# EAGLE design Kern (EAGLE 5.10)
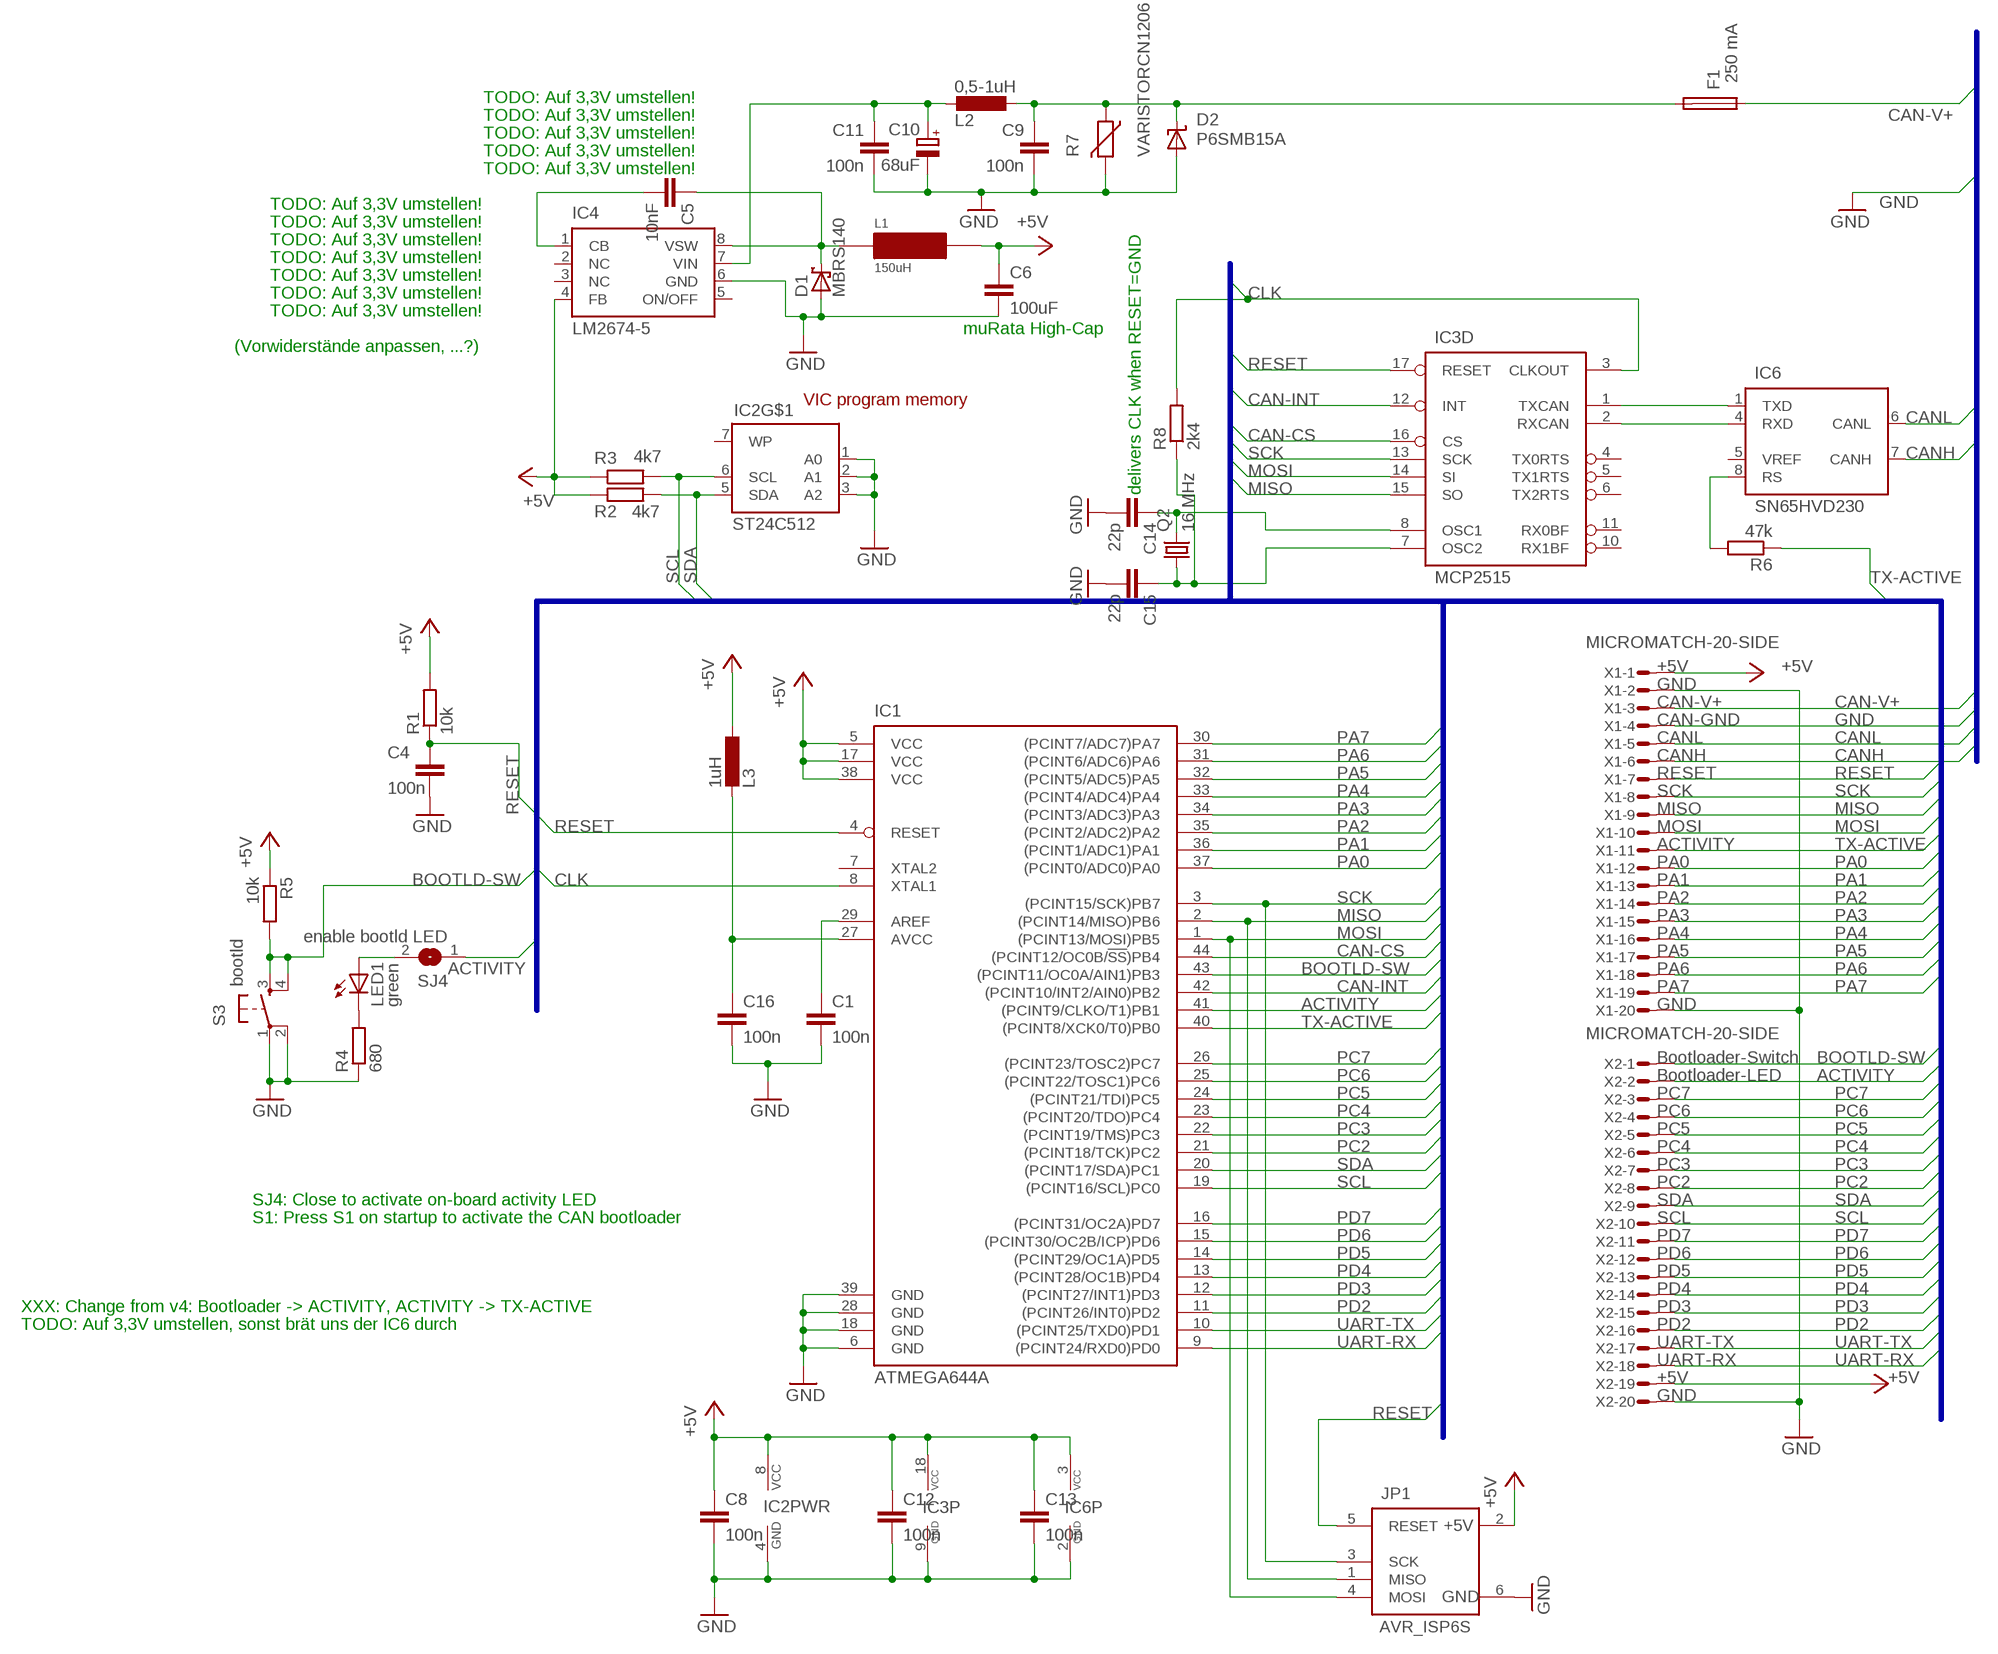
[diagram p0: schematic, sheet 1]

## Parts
C1  100n  C-EUC0805  [C0805]
C4  100n  C-EUC0805  [C0805]
C5  10nF  C-EUC0805  [C0805]
C6  100uF  C-EUC1206  [C1206]
C8  100n  C-EUC0805  [C0805]
C9  100n  C-EUC0805  [C0805]
C10  68uF  CPOL-EUD  [PANASONIC_D]
C11  100n  C-EUC0805  [C0805]
C12  100n  C-EUC0805  [C0805]
C13  100n  C-EUC0805  [C0805]
C14  22p  C-EUC0805  [C0805]
C15  22p  C-EUC0805  [C0805]
C16  100n  C-EUC0805  [C0805]
D1  MBRS140  MBRS130LT3  [SMB]
D2  P6SMB15A  P6SMBXXA  [SMB]
F1  250 mA  SICHERUNG-SMD  [SMD-HASF]
IC1  ATMEGA644A  [TQFP44]
IC2  ST24C512  ST24CXX_DIP  [DIL08]
IC3  MCP2515  MCP2515SO  [SO-18W]
IC4  LM2674-5  LM2674  [SO8]
IC6  SN65HVD230  PCA82C250  [DIL08]
JP1  AVR_ISP6S  [LEISTE_2X03]
L1  150uH  SPULEN-PIS28XX  [L-PIS28XX]
L2  0,5-1uH  L-EUL3216C  [L3216C]
L3  1uH  L-EUL3216C  [L3216C]
LED1  green  LEDCHIP-LED0805  [CHIP-LED0805]
Q2  16 MHz  CRYSTALHC49UP  [HC49UP]
R1  10k  R-EU_R0805  [R0805]
R2  4k7  R-EU_R0805  [R0805]
R3  4k7  R-EU_R0805  [R0805]
R4  680  R-EU_R0805  [R0805]
R5  10k  R-EU_R0805  [R0805]
R6  47k  R-EU_R0805  [R0805]
R7  VARISTORCN1206  [CT/CN1206]
R8  2k4  R-EU_R0805  [R0805]
S3  bootld  LSG  [SCHURTER_LSG]
SJ4  enable bootld LED  SJ  [SJ]
X1  MICROMATCH-20-SIDE  [MICROMATCH-20-SIDE]
X2  MICROMATCH-20-SIDE  [MICROMATCH-20-SIDE]

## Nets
+5V: C6.1 C8.1 C12.1 C13.1 IC1.5(VCC) IC1.17(VCC) IC1.38(VCC) IC2.8(PWR:VCC) IC3.18(P:VCC) IC4.4(FB) IC6.3(VCC) JP1.2(+5V) L1.2 L3.1 R1.2 R2.1 R3.1 R5.1 X1.1 X2.19
ACTIVITY: IC1.41((PCINT9/CLKO/T1)PB1) SJ4.1 X2.2
BOOTLD-SW: IC1.43((PCINT11/OC0A/AIN1)PB3) R5.2 S3.3(S) S3.4(S1) X2.1
CAN-CS: IC1.44((PCINT12/OC0B/!SS!)PB4) IC3.16(D:CS)
CAN-INT: IC1.42((PCINT10/INT2/AIN0)PB2) IC3.12(D:INT)
CAN-V+ [Power]: F1.1 X1.3
CANH: IC6.7(CANH) X1.6
CANL: IC6.6(CANL) X1.5
CLK: IC1.8(XTAL1) IC3.3(D:CLKOUT) R8.2
GND: C1.2 C4.2 C6.2 C8.2 C9.2 C10.- C11.2 C12.2 C13.2 C14.2 C15.2 C16.2 D1.A D2.A IC1.6(GND) IC1.18(GND) IC1.28(GND) IC1.39(GND) IC2.1(A0) IC2.2(A1) IC2.3(A2) IC2.4(PWR:GND) IC3.9(P:GND) IC4.6(GND) IC6.2(GND) JP1.6(GND) R4.1 R7.2 S3.1(P) S3.2(P1) X1.2 X1.4 X1.20 X2.20
MISO: IC1.2((PCINT14/MISO)PB6) IC3.15(D:SO) JP1.1(MISO) X1.9
MOSI: IC1.1((PCINT13/MOSI)PB5) IC3.14(D:SI) JP1.4(MOSI) X1.10
N$2: C5.1 D1.C IC4.8(VSW) L1.1
N$3: C1.1 IC1.29(AREF)
N$5 [Power]: C9.1 D2.C F1.2 L2.1 R7.1
N$6: LED1.C R4.2
N$7: C5.2 IC4.1(CB)
N$8 [Power]: C10.+ C11.1 IC4.7(VIN) L2.2
N$9: LED1.A SJ4.2
N$11: IC6.8(RS) R6.2
N$12: C14.1 IC3.8(D:OSC1) Q2.2
N$13: IC3.1(D:TXCAN) IC6.1(TXD)
N$14: IC3.2(D:RXCAN) IC6.4(RXD)
N$15: C16.1 IC1.27(AVCC) L3.2
N$16: C15.1 IC3.7(D:OSC2) Q2.1 R8.1
PA0: IC1.37((PCINT0/ADC0)PA0) X1.12
PA1: IC1.36((PCINT1/ADC1)PA1) X1.13
PA2: IC1.35((PCINT2/ADC2)PA2) X1.14
PA3: IC1.34((PCINT3/ADC3)PA3) X1.15
PA4: IC1.33((PCINT4/ADC4)PA4) X1.16
PA5: IC1.32((PCINT5/ADC5)PA5) X1.17
PA6: IC1.31((PCINT6/ADC6)PA6) X1.18
PA7: IC1.30((PCINT7/ADC7)PA7) X1.19
PC2: IC1.21((PCINT18/TCK)PC2) X2.8
PC3: IC1.22((PCINT19/TMS)PC3) X2.7
PC4: IC1.23((PCINT20/TDO)PC4) X2.6
PC5: IC1.24((PCINT21/TDI)PC5) X2.5
PC6: IC1.25((PCINT22/TOSC1)PC6) X2.4
PC7: IC1.26((PCINT23/TOSC2)PC7) X2.3
PD2: IC1.11((PCINT26/INT0)PD2) X2.16
PD3: IC1.12((PCINT27/INT1)PD3) X2.15
PD4: IC1.13((PCINT28/OC1B)PD4) X2.14
PD5: IC1.14((PCINT29/OC1A)PD5) X2.13
PD6: IC1.15((PCINT30/OC2B/ICP)PD6) X2.12
PD7: IC1.16((PCINT31/OC2A)PD7) X2.11
RESET: C4.1 IC1.4(RESET) IC3.17(D:RESET) JP1.5(RESET) R1.1 X1.7
SCK: IC1.3((PCINT15/SCK)PB7) IC3.13(D:SCK) JP1.3(SCK) X1.8
SCL: IC1.19((PCINT16/SCL)PC0) IC2.6(SCL) R3.2 X2.10
SDA: IC1.20((PCINT17/SDA)PC1) IC2.5(SDA) R2.2 X2.9
TX-ACTIVE: IC1.40((PCINT8/XCK0/T0)PB0) R6.1 X1.11
UART-RX: IC1.9((PCINT24/RXD0)PD0) X2.18
UART-TX: IC1.10((PCINT25/TXD0)PD1) X2.17
Unconnected: IC1.7(XTAL2) IC2.7(WP) IC3.4(D:TX0RTS) IC3.5(D:TX1RTS) IC3.6(D:TX2RTS) IC3.10(D:RX1BF) IC3.11(D:RX0BF) IC4.2(NC) IC4.3(NC) IC4.5(ON/OFF) IC6.5(VREF)

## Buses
PA[0..7],PC[2..7],PD[2..7],SCK,MISO,MOSI,CAN-CS,BOOTLD-SW,CAN-INT,TX-ACTIVE,ACTIVITY,SDA,SCL,UART-RX,UART-TX,CLK,RESET
CANL,CANH,CAN-V+,CAN-GND,GND

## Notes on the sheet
- TODO: Auf 3,3V umstellen!
- TODO: Auf 3,3V umstellen!
- TODO: Auf 3,3V umstellen!
- TODO: Auf 3,3V umstellen!
- TODO: Auf 3,3V umstellen!
- TODO: Auf 3,3V umstellen!
- TODO: Auf 3,3V umstellen!
- TODO: Auf 3,3V umstellen!
- TODO: Auf 3,3V umstellen!
- TODO: Auf 3,3V umstellen!
- TODO: Auf 3,3V umstellen!
- TODO: Auf 3,3V umstellen!
- muRata High-Cap
- (Vorwiderstände anpassen, ...?)
- VIC program memory
- delivers CLK when RESET=GND
- +5V
- GND
- CAN-V+
- CAN-GND
- CANL
- CANH
- RESET
- SCK
- MISO
- MOSI
- ACTIVITY
- PA0
- PA1
- PA2
- PA3
- PA4
- PA5
- PA6
- PA7
- GND
- Bootloader-Switch
- Bootloader-LED
- PC7
- PC6
- PC5
- PC4
- PC3
- PC2
- SJ4: Close to activate on-board activity LED | SDA
- S1: Press S1 on startup to activate the CAN bootloader | SCL
- PD7
- PD6
- PD5
- PD4
- XXX: Change from v4: Bootloader -> ACTIVITY, ACTIVITY -> TX-ACTIVE | PD3
- TODO: Auf 3,3V umstellen, sonst brät uns der IC6 durch | PD2
- UART-TX
- UART-RX
- +5V
- GND

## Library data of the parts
C1 C4-C6 C8 C9 C11-C16 = rcl:C-EU: CAPACITOR, European symbol
C10 = rcl:CPOL-EU: POLARIZED CAPACITOR, European symbol
D1 = diode:MBRS130LT3: Schottky Power Rectifier
D2 = 11my-ICs:P6SMBXXA: Suppressor diode
F1 = 11my-RCA:SICHERUNG: Fuse
IC1 = atmel:ATMEGA644: 8-bit Microcontroller with 64K Bytes In-System Programmable Flash Source: http://www.atmel.com/dyn/resources/prod_documents/doc2593.pdf
IC2 = 11my-ICs:ST24CXX: I²C EEPROM Bei den Atmeltypen ist der A2-Pin nicht angeschlossen! Bisher überprfte Größen: ST24C32 (4 kByte) ST24C64 (8 kByte) ST24C128 (16 kByte) ST24C256 (32 kByte)
IC3 = 11my-CAN:MCP2515: MC2515 Stand-Alone CAN Controller With SPI Interface
IC4 = lm2674-auml.se:LM2674
IC6 = 11my-CAN:PCA82C250: PCA82C250 CAN Bustreiber
JP1 = 11my-AVR:AVR_ISP6: ISP (In System Programming) Stecker fr AVRs ber diesen Anschlu kann ein AVR mit einem Standard ISP-Kabel direkt an einen Parallelport des PCs angeschlossen und programmiert werden.
L1 = 11my-RCA:SPULEN: SMD-Power-Induktivitten
L2 L3 = rcl:L-EU: INDUCTOR, European symbol
LED1 = led:LED: LED
Q2 = crystal:CRYSTAL: CRYSTAL
R1-R6 R8 = rcl:R-EU_: RESISTOR, European symbol
R7 = varistor:VARISTOR: VARISTOR
S3 = 11my-mechanics:LSG: Schurter LSG SMD-Taster
SJ4 = jumper:SJ: SMD solder JUMPER
X1 X2 = apbteam_con-amp-micromatch:MICROMATCH-20: Micro-MaTch 20 Straight connector: Suited for both, female and male.

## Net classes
0 default: width 0.15 mm
1 Power: width 0.5 mm

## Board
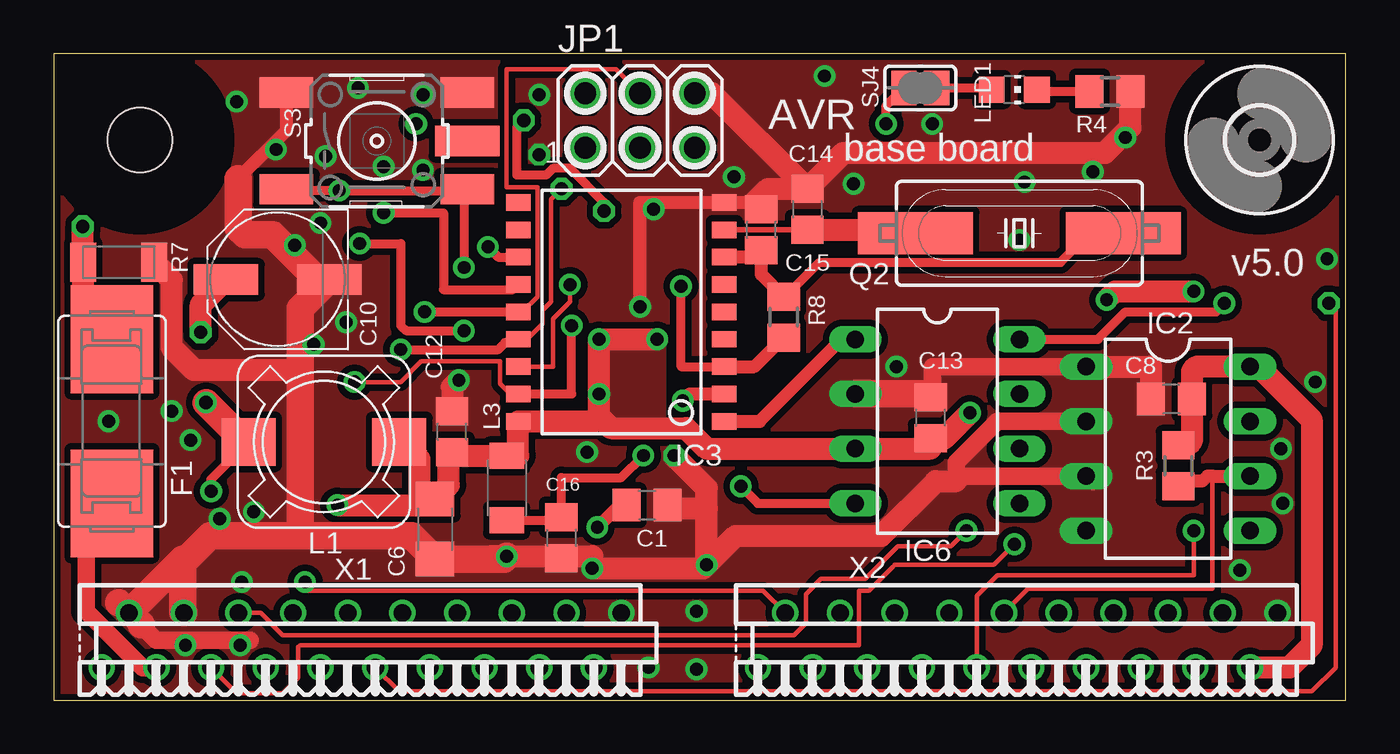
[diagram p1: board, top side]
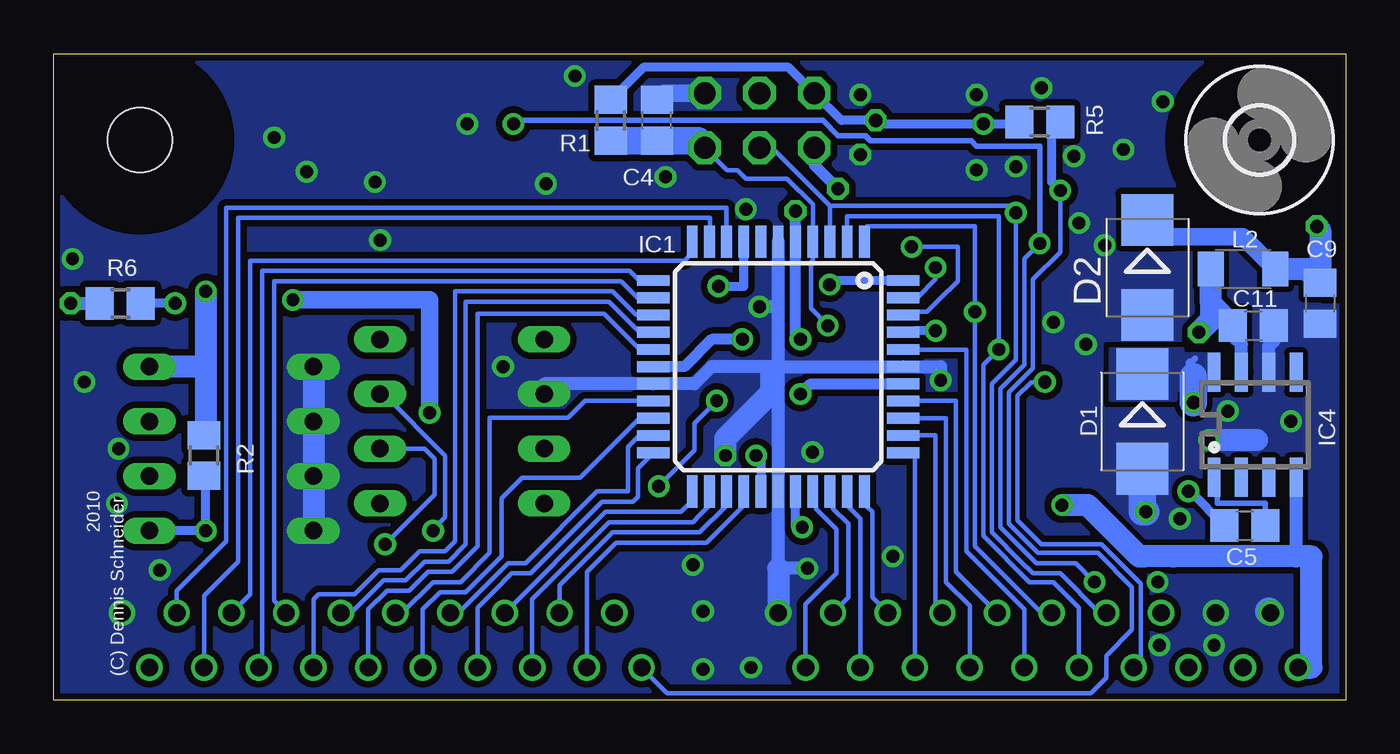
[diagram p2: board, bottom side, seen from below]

Size 60 x 30 mm. Coordinates in mm from the lower left corner, seen from the top.
Outline: 0,0 60,0 60,30 0,30 0,0
Copper layers (1+2*15+16): Top 0.035mm / dielectric 0.36mm / Route2 0.018mm / dielectric 0.71mm / Route15 0.018mm / dielectric 0.36mm / Bottom 0.035mm
Design rules "q-print.info *": minimum track width 6mil, minimum drill 0.3mm, track to track 6mil, track to pad 6mil, pad to pad 6mil, via to via 6mil, smd to smd 6mil, copper to edge 8mil, drill to drill 10mil, minimum pad ring 8mil, minimum via ring 8mil, stop-mask expansion 4mil, vias tented up to drill 16mil, thermal gap 10mil

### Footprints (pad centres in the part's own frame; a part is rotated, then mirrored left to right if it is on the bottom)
C0805 = smd 1.3 x 1.5: 1 -0.95,0; 2 0.95,0
C1206 = smd 1.6 x 1.8: 1 -1.4,0; 2 1.4,0
PANASONIC_D = smd 3 x 1.4: + 2.4,0; - -2.4,0
SMB = smd 2.4 x 2.4: A 2.2,0; C -2.2,0
SMD-HASF = smd 5 x 3.81: 1 -3.81,0; 2 3.81,0
TQFP44 = smd 1.5 x 0.5: 1 -5.8,4; 2 -5.8,3.2; 3 -5.8,2.4; 4 -5.8,1.6; 5 -5.8,0.8; 6 -5.8,0; 7 -5.8,-0.8; 8 -5.8,-1.6; 9 -5.8,-2.4; 10 -5.8,-3.2; 11 -5.8,-4; 23 5.8,-4; 24 5.8,-3.2; 25 5.8,-2.4; 26 5.8,-1.6; 27 5.8,-0.8; 28 5.8,0; 29 5.8,0.8; 30 5.8,1.6; 31 5.8,2.4; 32 5.8,3.2; 33 5.8,4 | smd 0.5 x 1.5: 12 -4,-5.8; 13 -3.2,-5.8; 14 -2.4,-5.8; 15 -1.6,-5.8; 16 -0.8,-5.8; 17 0,-5.8; 18 0.8,-5.8; 19 1.6,-5.8; 20 2.4,-5.8; 21 3.2,-5.8; 22 4,-5.8; 34 4,5.8; 35 3.2,5.8; 36 2.4,5.8; 37 1.6,5.8; 38 0.8,5.8; 39 0,5.8; 40 -0.8,5.8; 41 -1.6,5.8; 42 -2.4,5.8; 43 -3.2,5.8; 44 -4,5.8
DIL08 = drill 0.813 long: 1 -3.81,-3.81; 2 -1.27,-3.81; 3 1.27,-3.81; 4 3.81,-3.81; 5 3.81,3.81; 6 1.27,3.81; 7 -1.27,3.81; 8 -3.81,3.81
SO-18W = smd 0.762 x 1.143: 1 -5.08,-4.788; 2 -3.81,-4.788; 3 -2.54,-4.788; 4 -1.27,-4.788; 5 0,-4.788; 6 1.27,-4.788; 7 2.54,-4.788; 8 3.81,-4.788; 9 5.08,-4.788; 10 5.08,4.788; 11 3.81,4.788; 12 2.54,4.788; 13 1.27,4.788; 14 0,4.788; 15 -1.27,4.788; 16 -2.54,4.788; 17 -3.81,4.788; 18 -5.08,4.788
SO8 = smd 0.6 x 1.8: 1 -1.905,-2.44; 2 -0.635,-2.44; 3 0.635,-2.44; 4 1.905,-2.44; 5 1.905,2.44; 6 0.635,2.44; 7 -0.635,2.44; 8 -1.905,2.44
LEISTE_2X03 = drill 1.016 octagon: 1 -2.54,-1.27; 2 -2.54,1.27; 3 0,-1.27; 4 0,1.27; 5 2.54,-1.27; 6 2.54,1.27
L-PIS28XX = smd 2.2 x 2.5: 1 0,3.5; 2 0,-3.5
L3216C = smd 1.2 x 1.6: 1 -1.5,0; 2 1.5,0
CHIP-LED0805 = smd 1.2 x 1.2: A 0,-1.05; C 0,1.05
HC49UP = smd 5.334 x 1.93: 1 -4.826,0; 2 4.826,0
R0805 = smd 1.3 x 1.5: 1 -0.95,0; 2 0.95,0
CT/CN1206 = smd 1.2 x 1.8: 1 -1.65,0; 2 1.65,0
SCHURTER_LSG = smd 2.5 x 1.4: 1 -4.2,2.25; 2 4.2,2.25; 3 -4.2,-2.25; 4 4.2,-2.25 | smd 3 x 1.4: 5 4.2,0
SJ = smd 1.168 x 1.6: 1 -0.762,0; 2 0.762,0
3,0 = hole 3: 0,0
MICROMATCH-20-SIDE = drill 0.813 round: 1 12.065,1.27; 2 10.795,-1.27; 3 9.525,1.27; 4 8.255,-1.27; 5 6.985,1.27; 6 5.715,-1.27; 7 4.445,1.27; 8 3.175,-1.27; 9 1.905,1.27; 10 0.635,-1.27; 11 -0.635,1.27; 12 -1.905,-1.27; 13 -3.175,1.27; 14 -4.445,-1.27; 15 -5.715,1.27; 16 -6.985,-1.27; 17 -8.255,1.27; 18 -9.525,-1.27; 19 -10.795,1.27; 20 -12.065,-1.27

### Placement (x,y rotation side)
C1  27.54,9.05 0 top
C4  31.99,26.91 90 bottom
C5  4.68,8.1 0 bottom
C6  17.7,7.94 270 top
C8  51.91,13.97 180 top
C9  1.19,18.42 270 bottom
C10  10.4,19.53 180 top
C11  4.29,17.38 0 bottom
C12  18.49,12.46 90 top
C13  40.72,13.1 90 top
C14  35,22.78 90 top
C15  32.86,21.83 90 top
C16  23.57,7.54 270 top
D1  9.45,12.94 270 bottom
D2  9.21,20.08 270 bottom
F1  2.7,12.94 90 top
IC1  26.35,15.48 270 bottom
IC2  51.75,11.67 270 top
IC3  26.35,18.02 90 top
IC4  4.21,12.78 0 bottom
IC6  41.04,12.94 270 top
JP1  27.23,26.91 0 top
L1  12.54,11.99 90 top
L2  4.76,20 180 bottom
L3  21.03,9.84 270 top
LED1  44.61,28.34 270 top
Q2  44.85,21.67 180 top
R1  34.13,26.91 90 bottom
R2  53.02,11.35 270 bottom
R3  52.23,10.87 270 top
R4  49.05,28.26 180 top
R5  14.21,26.83 0 bottom
R6  56.91,18.42 0 bottom
R7  3.02,20.32 0 top
R8  33.89,17.78 270 top
S3  15,25.96 0 top
SJ4  40.24,28.42 0 top
U$1  [3,0]  56,26 0 top
U$2  [3,0]  4,26 0 bottom
X1  14.29,2.78 180 top
X2  44.77,2.78 180 top

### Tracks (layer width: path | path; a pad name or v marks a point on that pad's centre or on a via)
+5V  (via drill 0.6, 0.61)
  Top 0.406: v21.83,26.91 21.51,26.59 21.51,24.37 22.86,24.37 23.18,24.69 23.97,24.69 25.56,23.1 v25.56,22.7
  Top 1.016: 25.32,13.18 v25.32,14.21 v25.32,16.75 v28.02,16.75 | 25.32,13.18 25.08,12.94 IC3.18 21.57,11.34 L3.1 18.66,11.34 C12.1 18.34,11.35 18.34,9.97 C6.1 | IC2.8 56.04,15.48 | 56.2,15.4 55.64,15.4 IC2.8 | L1.2 15.48,11.99 16.03,11.43 16.75,11.43 16.99,11.19 16.99,9.37 17.02,9.34 C6.1 | v13.18,9.05 17.49,9.05 17.7,9.26 C6.1 | IC2.8 53.18,15.48 arc90 52.86,15.16 C8.1 52.86,12.14 arc-90 52.54,11.82 R3.1 | v52.94,18.97 49.29,18.97 v48.9,18.57 | v42.55,13.34 41.36,12.15 C13.1 40.72,11.67 IC6.3 30.32,11.67 29.37,12.62 25.88,12.62 25.32,13.18 | X2.19 57.39,1.51 58.42,2.54 58.42,13.02 55.96,15.48 IC2.8
  Bottom 0.406: JP1.2 | JP1.2 23.42,26.91 v21.83,26.91 21.67,26.75 v16.83,26.75 15.24,26.75 R5.1 | JP1.2 25.88,29.37 32.62,29.37 R1.2
  Bottom 0.508: v25.32,16.75 25.56,16.75 IC1.5 v25.56,22.7 | IC1.17 30.72,15.48 29.45,16.75 v28.02,16.75 | IC1.38 24.85,14.68 v25.32,14.21
  Bottom 0.61: 2.3,6.67 IC4.4
  Bottom 0.813: v42.55,13.34 42.55,18.57 v48.9,18.57
  Bottom 1.016: X1.1 1.59,1.51 1.59,6.67 2.3,6.67 8.02,6.67 | 8.02,6.67 | 8.02,6.67 | 8.02,6.67 9.37,6.67 | 52.94,15.48 IC2.8 | 52.94,15.48 52.94,12.3 R2.1 | v13.18,9.05 11.99,9.05 9.6,6.67 9.37,6.67 | 9.37,6.67 | v52.94,18.97 52.94,15.48
  pour Top: 25.4,12.7 28.26,12.7 28.26,16.51 25.4,16.51
ACTIVITY  (via drill 0.6)
  Top 0.203: v11.67,5.48 11.67,5.08 32.94,5.08 X2.2
  Top 0.406: v19.05,17.14 16.35,17.14 16.11,17.38 16.11,21.19 v14.21,21.19 | v38.66,26.75 38.66,27.59 SJ4.1
  Bottom 0.203: 20,17.14 20,17.08 IC1.41 | v11.67,5.48 12.54,6.35 14.37,6.35 16.03,8.02 16.03,14.45 14.92,15.56 14.92,20.48 v14.21,21.19 | v19.05,17.14
  Bottom 0.254: v14.21,21.19 14.21,25.72 17.14,25.72 17.38,25.96 22.07,25.96 22.3,26.19 23.57,26.19 24.29,26.91 38.5,26.91 v38.66,26.75
  Bottom 0.406: v19.05,17.14 20,17.14
BOOTLD-SW  (via drill 0.6)
  Top 0.204: 19.05,23.65 19.2,23.65 S3.4
  Top 0.406: 19.05,23.65 v19.05,20.08 | S3.3 10.8,23.65 v13.26,23.65 19.15,23.65 S3.4
  Bottom 0.203: v19.05,20.08 19.05,19.53 19.92,18.65 20.53,18.65 IC1.43 | v13.26,23.65 13.26,20.8 14.53,19.53 14.53,15.4 15.64,14.29 15.64,8.18 14.29,6.83 11.51,6.83 9.92,5.24 9.92,3.25 11.11,2.06 11.11,1.03 11.83,0.32 31.51,0.32 X2.1
  Bottom 0.406: v13.26,23.65 13.65,24.05 13.65,26.35 13.26,26.75 R5.2
CAN-CS  (via drill 0.6)
  Top 0.203: IC3.16 23.18,15.48 23.18,17.7 23.97,18.49 v23.97,19.29
  Bottom 0.406: IC1.44 23.78,19.48 v23.97,19.29
CAN-INT  (via drill 0.6)
  Top 0.203: 21.35,20.56 IC3.12
  Top 0.406: 21.35,20.56 20.64,20.56 v20.16,21.04
  Bottom 0.203: IC1.42 20.55,18.02 19.45,18.02 18.89,18.57 | 18.89,18.57 | 18.89,18.57 18.02,19.45 18.02,21.04 v20.16,21.04
CAN-V+
  Top 0.813: X1.3 4.13,1.51 1.51,4.13 1.51,7.94 F1.1
CANH  (via drill 0.61)
  Top 0.203: X1.6 9.6,4.05 10.64,3.02 34.37,3.02 34.92,3.57 34.92,4.92 35.64,5.64 37.7,5.64 39.21,7.14 41.67,7.14 v42.39,7.86
  Bottom 0.203: 41.83,11.35 41.83,8.49 42.39,7.94 v42.39,7.86
  Bottom 0.204: IC6.7 44.69,14.21 41.83,11.35
CANL  (via drill 0.61)
  Top 0.203: 38.97,6.19 37.86,5.08 37.39,5.08 37.39,2.54 11.43,2.54 11.35,2.46 11.35,1.03 10.64,0.32 8.49,0.32 X1.5
  Top 0.204: 38.97,6.19 39.05,6.27 43.66,6.27 v44.61,7.22
  Bottom 0.203: 42.31,11.19 42.31,9.53 v44.61,7.22
  Bottom 0.204: IC6.6 42.78,11.67 42.31,11.19
CLK  (via drill 0.6)
  Top 0.406: IC3.3 29.13,15.48 v29.13,19.21 | IC3.3
  Top 0.61: IC3.3 32.54,15.48 R8.2
  Bottom 0.406: v29.13,19.21 27.95,19.21 IC1.8
GND  (via drill 0.6)
  Top 0.61: v27.23,18.26 27.23,23.1 IC3.9 32.54,23.1 C15.2 | 8.57,24.21 10.8,26.44 S3.1
  Top 0.813: X1.2 4.76,2.78 | 40.8,14.05 40.8,15.48 IC2.1 | 4.76,2.78 arc90 4.76,2.78 | 4.76,2.78 9.13,2.78 | IC2.2 43.81,12.94 41.91,11.03 41.91,10.16 42.15,10.4 48.02,10.4 48.26,10.16
  Top 1.016: IC2.1 50.96,15.48 C8.2 | C13.2 40.8,14.05 | v21.04,6.67 20.32,6.67 20.32,6.68 25,6.68 v25,6.11 26.91,6.11 | v30.32,6.27 30.16,6.11 26.83,6.11 | v18.81,14.84 18.49,14.53 C12.2 | 32.54,23.1 33.17,23.73 C14.2 | C14.2 30.56,28.18 JP1.6 | X1.2 3.57,4.05 | v30.32,6.27 31.67,7.62 38.42,7.62 40.96,10.16 41.91,10.16 | v30.32,6.27 30.32,8.89 | 30.32,8.89 30.32,9.84 v28.81,11.35 | C14.2 36.67,25.4 48.82,25.4 50.01,26.59 R4.1 | R7.2 5.48,19.51 5.48,16.35 6.51,15.32 11.35,15.32 11.43,15.24 | C1.2 28.65,8.89 30.32,8.89
  Top 1.27: X1.2 | v21.04,6.67 20.9,6.54 C6.2 16.62,7.62 11.43,7.62 | X1.2 5.98,6.54 5.98,6.35 | 5.98,6.35 5.98,4.1 X1.4 | 11.43,7.62 7.25,7.62 5.98,6.35 | 11.43,7.62 11.43,15.24 11.43,18.16 C10.- 12.22,19.53 10.16,21.59 8.89,21.59 8.57,21.91 8.57,24.21 | C13.2 40.56,14.21 IC6.2 | 3.02,4.52 | 4.05,3.49
  Bottom 0.61: 26.35,15.48 IC1.39 18.81,15.48 v18.81,14.84 | 26.35,18.26 IC1.6 | 26.35,15.48 IC1.28 26.35,6.11 v25,6.11 | IC6.2 37.23,14.68 IC1.18 30.25,14.68 29.45,15.48 26.35,15.48 | 26.35,15.48 26.35,18.26 | 26.35,18.26 v27.23,18.26 | IC4.6 3.57,16.43 3.34,16.67 C11.2
  Bottom 0.813: JP1.6 31.67,28.18 C4.2
  Bottom 1.016: 4.13,12.06 v6.35,12.06 | IC2.1 IC2.2 IC2.3 IC2.4 | 26.35,6.11 X1.20 | v28.81,11.35 28.81,12.14 26.67,14.29 26.67,15.24
  Bottom 1.27: v9.29,8.73 9.45,8.73 D1.A | 3.57,4.13
  other vias: 7.7,8.41 58.58,14.76 55.09,6.03 24.77,11.51 39.13,15.48 12.38,22.15 6.11,2.54 8.65,2.54 44.85,21.35 27.86,22.78 27.62,1.51 8.49,27.78 48.26,24.53 14.13,28.42 22.54,28.1 35.8,28.97 37.15,23.97 49.77,26.11 45.09,24.05 15.32,24.77 12.62,25.24 2.54,12.94 40.8,26.75 10.32,25.56 17.15,24.61 8.73,5.48 5.48,13.41 13.57,17.54 31.59,24.29 12.07,16.51 57.07,9.13 56.99,11.67 22.54,25.32 17.15,28.1 59.13,20.48 11.19,21.11 29.85,4.13 29.85,1.43
  pour Bottom (isolate 0.305, rank 5, no thermals): 0,0 60,0 60,30 0,30
  pour Top (isolate 0.305, rank 5, no thermals): 0,0 0,30 60,30 60,0
  pour Bottom (isolate 0.254, rank 5, no thermals): 1.27,23.26 1.27,6.51 12.06,6.51 12.14,23.26
MISO  (via drill 0.6, 0.61)
  Top 0.203: 21.35,16.75 IC3.15 21.99,16.75 22.7,17.46 22.7,18.1 23.1,18.5 23.1,20.72 | 23.1,20.72 | 23.1,20.72 23.1,23.26 23.65,23.81 v23.57,23.73
  Top 0.406: v16.11,16.27 20.64,16.27 20.95,16.59 21.41,16.59 IC3.15
  Bottom 0.203: IC1.2 23.15,22.46 16.11,22.46 v16.11,16.27 | X1.9 12.38,4.29 13.18,5.08 | 13.18,5.08 13.57,5.48 14.68,5.48 16.83,7.62 16.83,15.56 v16.11,16.27 | 13.18,5.08 | v16.11,16.27
  Bottom 0.508: v23.57,23.73 24.69,24.84 JP1.1
MOSI  (via drill 0.6)
  Top 0.203: IC3.14 21.75,18.02 22.46,18.73 22.46,21.11 | 21.03,29.29 26.11,29.29 JP1.4
  Top 0.204: 21.03,29.29 21.03,23.81 22.46,23.81 22.46,21.11
  Top 0.406: v17.22,18.02 IC3.14
  Bottom 0.203: IC1.1 22.23,21.28 22.23,21.99 17.22,21.99 v17.22,18.02 17.22,7.14 14.13,4.05 X1.10
N$2  (via drill 0.61)
  Top 0.406: v7.3,9.68 7.3,10.25 L1.1
  Top 1.27: v7.06,13.81 8.89,11.99 L1.1
  Bottom 0.254: 7.22,15.64 6.99,15.88
  Bottom 0.406: 7.06,15 7.22,15.16 7.22,15.64 | v7.3,9.68 7.22,9.68 C5.1
  Bottom 1.27: v7.06,13.81 7.06,15
  pour Bottom (no thermals): 5.95,14.45 7.94,14.45 7.94,13.97 10.87,13.97 10.87,16.27 7.62,16.27 7.62,16.03 5.95,16.03
N$3  (via drill 0.6)
  Top 0.61: v25.24,8.02 26.27,9.05 C1.1
  Bottom 0.406: v25.24,8.02 25.55,8.02 IC1.29
N$5  (via drill 0.61)
  Top 1.016: F1.2 1.37,18.08 R7.1 1.35,20.34 v1.35,21.99
  Bottom 0.813: D2.C 9.11,22.28 8.33,21.51 4.77,21.51 L2.1
  Bottom 1.016: v1.35,21.99 1.19,21.83 C9.1 1.83,20 L2.1
N$6
  Top 0.406: 48.1,28.34 R4.2 45.74,28.26 LED1.C
N$7
  Bottom 0.254: IC4.1 5.95,10.34 5.95,9.13 3.73,9.13 C5.2
N$8  (via drill 0.61)
  Top 1.016: v6.83,17.07 6.83,18.36 C10.+
  Bottom 0.61: IC4.7 4.84,16.51 5.08,16.75 5.08,17.23 C11.1
  Bottom 1.016: C11.1 6.26,18.41 | 6.26,18.41 L2.2 | 6.26,18.41 6.26,17.63 v6.83,17.07
N$9
  Top 0.406: SJ4.2 43.48,28.42 LED1.A
N$11  (via drill 0.61)
  Top 0.406: IC6.8 48.5,16.75 49.77,18.02 53.98,18.02 v54.37,18.41
  Top 0.61: IC6.8
  Bottom 0.406: v54.37,18.41 R6.2 | R6.2
  Bottom 0.61: v54.37,18.41
N$12
  Top 0.203: IC3.8 31.51,21.83 | Q2.2 39.53,21.67
  Top 0.254: IC3.8 C14.1
  Top 0.305: C14.1
  Top 1.016: C14.1 39.86,21.83 Q2.2
N$13
  Top 0.61: IC6.1 36.59,16.75 32.78,12.94 IC3.1
N$14  (via drill 0.6)
  Top 0.203: IC3.2 30.98,14.05
  Top 0.406: IC6.4 32.7,9.13 v31.91,9.92
  Top 0.61: IC3.2 29.53,14.21 v29.21,13.89
  Bottom 0.203: v31.91,9.92 30.24,11.59 30.24,12.86 v29.21,13.89
N$15  (via drill 0.6)
  Top 0.406: L3.2 23.57,8.34 C16.1 23.57,10.32 26.35,10.32 v27.38,11.35
  Bottom 0.406: v27.38,11.35 27.15,11.35 IC1.27
N$16
  Top 0.203: IC3.7 31.43,20.56 | 48.96,20.95 Q2.1
  Top 0.204: 49.37,20.8 49.37,20.95 48.96,20.95 47.39,20.95 | 47.39,20.95 47.13,20.95 | 47.39,20.95 48.9,20.95 49.53,21.59
  Top 0.406: 47.39,20.95 46.75,20.32 35.56,20.32 34.37,19.13 34.29,19.13 R8.1
  Top 0.61: IC3.7 32.54,20.56 C15.1 32.86,19.76 R8.1
PA0
  Bottom 0.203: IC1.37 18.1,13.89 18.1,5.95 X1.12
PA1
  Bottom 0.203: IC1.36 18.57,13.08 18.57,5.48 17.46,4.37 X1.13
PA2
  Bottom 0.203: X1.14 | X1.14 19.05,4.37 19.05,12.3 20.55,12.3 IC1.35
PA3
  Bottom 0.203: IC1.34 20,11.48 X1.15
PA4
  Bottom 0.203: IC1.33 22.23,9.68 22.23,8.97 21.99,8.73 21.99,4.76 X1.16
PA5
  Bottom 0.203: X1.17 22.54,8.41 23.1,8.97 23.1,9.62 IC1.32
PA6
  Bottom 0.203: IC1.31 23.95,9.05 23.81,9.05 23.81,8.89 23.1,8.18 23.1,4.76 X1.18
PA7
  Bottom 0.203: 24.77,9.67 IC1.30 24.75,9.05 24.61,9.05 24.61,8.89 23.65,7.94 23.65,5.87 25.08,4.45 X1.19
PC2
  Bottom 0.203: IC1.21 32.65,12.28 32.73,12.36 33.34,11.75 33.34,9.68 34.77,9.68 38.1,6.35 38.89,6.35 41.2,4.05 X2.8
PC3
  Bottom 0.203: 39.53,5.08 40.32,4.29 X2.7 | IC1.22 32.86,10.77 32.86,9.45 33.1,9.21 34.53,9.21 37.86,5.87 38.73,5.87 39.53,5.08 | 39.53,5.08
PC4
  Bottom 0.203: X2.6 34.37,8.73 30.88,8.73 30.56,9.05 30.35,9.05 IC1.23
PC5
  Bottom 0.203: IC1.24 29.61,9.62 29.61,8.97 30,8.57 | 30,8.57 | 30,8.57 30.32,8.26 34.21,8.26 37.78,4.68 X2.5
PC6
  Bottom 0.203: IC1.25 28.81,9.62 28.81,8.97 30,7.78 34.05,7.78 36.51,5.32 X2.4
PC7
  Bottom 0.203: IC1.26 28.02,9.61 28.02,8.97 29.69,7.3 33.89,7.3 35.24,5.95 X2.3
PD2
  Bottom 0.203: IC1.11 30.4,21.23 30.4,20.72 30.72,20.4 50.88,20.4 50.88,4.92 X2.16
PD3
  Bottom 0.203: IC1.12 32.81,19.48 33.26,19.92 50.32,19.92 50.32,1.67 X2.15
PD4
  Bottom 0.203: IC1.13 32.89,18.68 33.66,19.45 49.77,19.45 49.77,4.6 X2.14
PD5
  Bottom 0.203: IC1.14 32.96,17.88 34.05,18.97 41.35,18.97 41.35,7.38 41.83,6.91 43.02,6.91 43.89,6.03 44.93,6.03 46.04,4.92 47.7,4.92 47.94,4.68 X2.13
PD6
  Bottom 0.203: IC1.15 32.79,17.08 34.21,18.5 40.88,18.5 40.88,7.22 41.67,6.43 42.78,6.43 43.66,5.56 44.69,5.56 46.2,4.05 X2.12
PD7
  Bottom 0.203: IC1.16 32.79,16.28 34.45,17.94 40.32,17.94 40.32,7.14 41.51,5.95 42.62,5.95 43.5,5.08 44.53,5.08 45.4,4.21 X2.11
RESET  (via drill 0.6, 0.61)
  Top 0.203: IC3.17 21.19,14.21 20.72,14.68 20.72,15.72 17.07,15.72 16.11,14.76 v13.97,14.76
  Top 0.406: v24.05,17.38 24.05,14.21 IC3.17
  Bottom 0.203: 9.6,1.75 X1.7 9.53,1.83 9.53,5.4 11.35,7.22 14.13,7.22 15.24,8.33 15.24,14.13 14.61,14.76 v13.97,14.76 | 25.96,24.21 24.75,23.01 IC1.4 24.75,20.41 24.84,20.32 24.84,18.18 v24.05,17.38 | 28.26,24.61 28.73,24.61 JP1.5
  Bottom 0.204: 25.96,24.21 27.86,24.21 28.26,24.61
  Bottom 1.27: C4.1 R1.1 | C4.1 | C4.1 30.09,25.96 JP1.5
SCK  (via drill 0.6)
  Top 0.203: IC3.13 21.27,19.29 21.27,19.13
  Top 0.406: v15.32,22.62 18.1,22.62 18.1,19.05 21.33,19.05 IC3.13
  Bottom 0.203: X1.8 11.43,4.05 13.26,5.87 14.53,5.87 15.08,6.43 16.43,7.78 16.43,14.68 15.32,15.8 v15.32,22.62 15.32,22.94 23.95,22.94 | 23.95,22.94 IC1.3 | 23.95,22.94 26.65,25.64 JP1.3
SCL
  Top 0.203: 53.82,10.4 53.82,5.16 45.24,5.16 X2.10
  Top 0.61: R3.2 52.46,10.16 53.34,10.16 53.58,10.4 53.82,10.4 IC2.6
  Bottom 0.203: IC1.19 35.32,13.89 36.12,13.1 39.77,13.1 39.77,6.83 41.12,5.48 42.39,5.48 43.81,4.05 X2.10 | IC1.19 | IC1.19 31.99,13.89
SDA  (via drill 0.6)
  Top 0.203: v52.94,7.86 52.94,5.79 43.81,5.79 42.86,4.84 X2.9
  Bottom 0.203: 32.13,13.1 32.78,13.1 33.26,12.62 | 33.26,12.62 | 32.13,13.1 IC1.20 | 32.13,13.1 31.99,13.1 | X2.9 42.86,4.21 42.07,5 40.88,5 39.21,6.67 39.21,9.37 38.26,10.32 35.56,10.32 33.26,12.62
  Bottom 0.254: 52.94,10.4 R2.2 | v52.94,7.86
  Bottom 0.406: 52.94,10.4 v52.94,7.86 IC2.5
TX-ACTIVE  (via drill 0.61)
  Top 0.203: X1.11 16.03,0.4 58.42,0.4 59.53,1.51 59.53,18.1 v59.21,18.41
  Bottom 0.203: IC1.40 17.62,16.27 17.62,6.91 14.92,4.21 X1.11 | R6.1 57.86,17.78
  Bottom 0.61: v59.21,18.41 R6.1 | R6.1
UART-RX
  Bottom 0.203: IC1.9 28.75,22.86 51.99,22.86 51.99,7.38 54.29,5.08 X2.18
UART-TX
  Bottom 0.203: IC1.10 29.53,21.28 29.53,22.38 51.44,22.38 51.44,6.43 53.02,4.84 X2.17

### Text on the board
tPlace: AVR | 1 | base board
bPlace: 2010 | (C) Dennis Schneider
tNames: v5.0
